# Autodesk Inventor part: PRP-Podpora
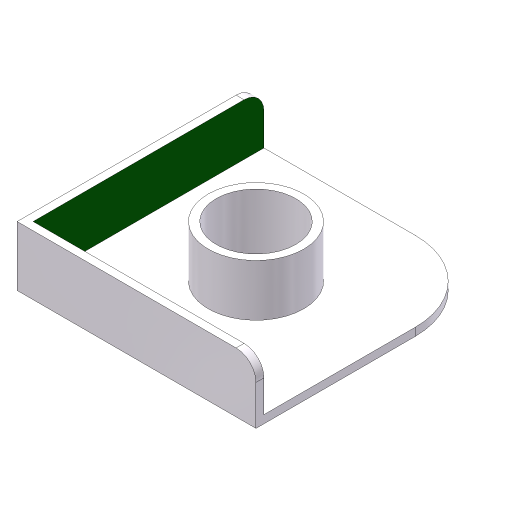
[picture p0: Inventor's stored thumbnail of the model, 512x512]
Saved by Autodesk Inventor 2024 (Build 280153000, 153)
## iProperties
Company: ATC
Shininess: 21.0
Length Units: 11269
Angle Units: 11279
Time Units: 11290
Mass Units: 11283
Length Display Precision: 3
Angle Display Precision: 2
Compacted: True
Created: 2023-03
Part Number: PRP-Podpora
Document SubType Name: Modeling
Designer: Andrzej Jaskulski
Material: Kurs-AJ
Density: 1 g/cm^3
Mass: 11.2231 g
Surface Area: 118.487 cm^2
Volume: 11.2231 cm^3
Appearance: Kurs-AJ
Checked By: A.J.
Engr Approved By: Andrzej Jaskulski
Mfg Approved By: Andrzej Jaskulski
Authority: A.J.
Density: 0.0
Volumn: 0.0
Area: 0.0
PropertySet Name: Model Information
Control State: 0
Master: False
Checked Out: False
Title: A.J.: Kurs R2024-MEP
Author: Andrzej Jaskulski
Revision Number: 1/24
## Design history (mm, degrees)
sketch "Sketch1"
  geometry: L1 (0, 0)-(60, 0); L2 (60, 0)-(60, 60); L3 (60, 60)-(0, 60); L4 (0, 60)-(0, 0)
  constraints: 8 end point, 2 parallel, 1 horizontal, 1 perpendicular, 1 other
  dimensions: "d0" = 60 distance of L1.start L1.end (= x); "d1" = 60 distance of L1.end L2.end (= y)
extrude "Baza" new body sketch "Sketch1" distance "d2" = 15 (= h); taper "d3" = 0 deg
sketch "Sketch3"
  geometry: L1 (0, 0)-(0, 60) reference; L2 (60, 0)-(0, 0) reference; 1 further point
  dimensions: "d9" = 30 distance from line of L1 point (30, 30) (= Lx); "d10" = 30 distance from line of L2 point (30, 30) (= Ly)
hole "Otwór" sketch "Sketch3" diameter "d7" = 20; stored, may be unused: countersink angle "d18" = 60 deg, drill point angle "d20" = 118 deg; dims "d8" = 6, "d16" = 4, "d17" = 2, "d19" = 8
fillet "Zaokrąglenie1" dims "d4" = 20 (= d)
fillet "Zaokrąglenie2" dims "d5" = 5 (= 0.5 x r)
feature "Skorupa1" dims "d6" = 2
node "Bryła1"
node "Korpusy bryłowe"
node "Korpusy powierzchniowe"
other parameters: "x" = 60 [user parameter; used in 1 equation term], "y" = 60 [user parameter; used in 1 equation term], "h" = 15 [user parameter; used in 1 equation term], "Lx" = 30 [user parameter; used in 1 equation term], "Ly" = 30 [user parameter; used in 1 equation term], "L2" = 1 [user parameter]
